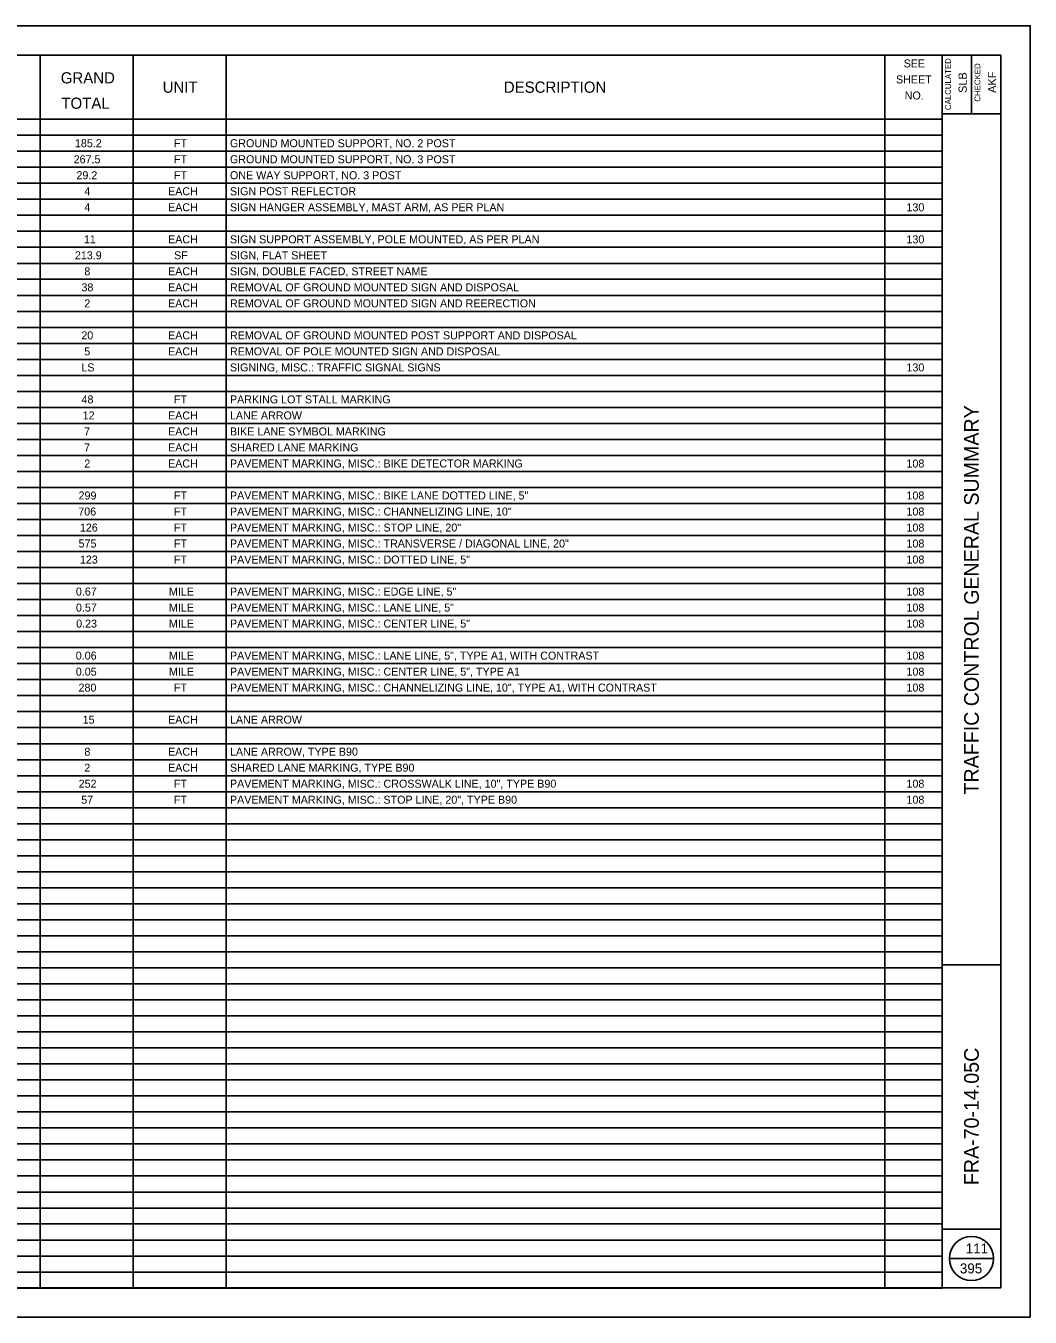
# Model space of a CAD drawing. Extents: x 1822379 to 1824724, y 710341 to 711455.
# Drawn here: x 1822396.01 to 1822413.11, y 711198.87 to 711220.87 of the extents above; entities that cross this region are included whole.
import ezdxf

# ---------------------------------------------------------------- set-up
doc = ezdxf.new("R2010")
doc.units = 0
for name, color, linetype in [('SH_Border', 7, 'Continuous'), ('SH_Cut_Line', 7, 'Continuous'), ('SH_Data', 7, 'Continuous'), ('SH_Text', 7, 'Continuous'), ('TX_P_20', 7, 'Continuous')]:
    doc.layers.add(name, color=color, linetype=linetype)

msp = doc.modelspace()

# ---------------------------------------------------------------- linework, layer by layer
at = {"layer": 'SH_Border'}
for p, q in [((1822411.613, 711199.366), (1822411.613, 711220.366)), ((1822412.113, 711220.366), (1822412.113, 711219.366)), ((1822411.613, 711219.366), (1822412.613, 711219.366)), ((1822411.613, 711204.866), (1822412.613, 711204.866)), ((1822411.613, 711200.366), (1822412.613, 711200.366))]:
    msp.add_line(p, q, dxfattribs=at)
msp.add_lwpolyline([(1822381.113, 711220.366), (1822412.613, 711220.366), (1822412.613, 711199.366), (1822381.113, 711199.366)], close=True, dxfattribs=at)
at = {"layer": 'SH_Cut_Line'}
msp.add_lwpolyline([(1822379.113, 711198.866), (1822413.113, 711198.866), (1822413.113, 711220.866), (1822379.113, 711220.866)], close=True, dxfattribs=at)
at = {"layer": 'SH_Data'}
for p, q in [((1822393.438, 711220.366), (1822411.613, 711220.366)), ((1822396.255, 711220.366), (1822396.255, 711199.362)), ((1822397.837, 711220.366), (1822397.837, 711199.362)), ((1822399.419, 711220.366), (1822399.419, 711199.362)), ((1822410.64, 711220.366), (1822410.64, 711199.362)), ((1822411.613, 711220.366), (1822411.613, 711199.362)), ((1822381.113, 711219.274), (1822411.613, 711219.274)), ((1822381.113, 711219.002), (1822411.613, 711219.002)), ((1822381.113, 711218.729), (1822411.613, 711218.729)), ((1822381.113, 711218.456), (1822411.613, 711218.456)), ((1822381.113, 711218.183), (1822411.613, 711218.183)), ((1822381.113, 711217.911), (1822411.613, 711217.911)), ((1822381.113, 711217.638), (1822411.613, 711217.638)), ((1822381.113, 711217.365), (1822411.613, 711217.365)), ((1822381.113, 711217.092), (1822411.613, 711217.092)), ((1822381.113, 711216.819), (1822411.613, 711216.819)), ((1822381.113, 711216.547), (1822411.613, 711216.547)), ((1822381.113, 711216.274), (1822411.613, 711216.274)), ((1822381.113, 711216.001), (1822411.613, 711216.001)), ((1822381.113, 711215.728), (1822411.613, 711215.728)), ((1822381.113, 711215.456), (1822411.613, 711215.456)), ((1822381.113, 711215.183), (1822411.613, 711215.183)), ((1822381.113, 711214.91), (1822411.613, 711214.91)), ((1822381.113, 711214.637), (1822411.613, 711214.637)), ((1822381.113, 711214.364), (1822411.613, 711214.364)), ((1822381.113, 711214.092), (1822411.613, 711214.092)), ((1822381.113, 711213.819), (1822411.613, 711213.819)), ((1822381.113, 711213.546), (1822411.613, 711213.546)), ((1822381.113, 711213.273), (1822411.613, 711213.273)), ((1822381.113, 711213.001), (1822411.613, 711213.001)), ((1822381.113, 711212.728), (1822411.613, 711212.728)), ((1822381.113, 711212.455), (1822411.613, 711212.455)), ((1822381.113, 711212.182), (1822411.613, 711212.182)), ((1822381.113, 711211.909), (1822411.613, 711211.909)), ((1822381.113, 711211.637), (1822411.613, 711211.637)), ((1822381.113, 711211.364), (1822411.613, 711211.364)), ((1822381.113, 711211.091), (1822411.613, 711211.091)), ((1822381.113, 711210.818), (1822411.613, 711210.818)), ((1822381.113, 711210.545), (1822411.613, 711210.545)), ((1822381.113, 711210.273), (1822411.613, 711210.273)), ((1822381.113, 711210), (1822411.613, 711210)), ((1822381.113, 711209.727), (1822411.613, 711209.727)), ((1822381.113, 711209.454), (1822411.613, 711209.454)), ((1822381.113, 711209.182), (1822411.613, 711209.182)), ((1822381.113, 711208.909), (1822411.613, 711208.909)), ((1822381.113, 711208.636), (1822411.613, 711208.636)), ((1822381.113, 711208.363), (1822411.613, 711208.363)), ((1822381.113, 711208.09), (1822411.613, 711208.09)), ((1822381.113, 711207.818), (1822411.613, 711207.818)), ((1822381.113, 711207.545), (1822411.613, 711207.545)), ((1822381.113, 711207.272), (1822411.613, 711207.272)), ((1822381.113, 711206.999), (1822411.613, 711206.999)), ((1822381.113, 711206.727), (1822411.613, 711206.727)), ((1822381.113, 711206.454), (1822411.613, 711206.454)), ((1822381.113, 711206.181), (1822411.613, 711206.181)), ((1822381.113, 711205.908), (1822411.613, 711205.908)), ((1822381.113, 711205.635), (1822411.613, 711205.635)), ((1822381.113, 711205.363), (1822411.613, 711205.363)), ((1822381.113, 711205.09), (1822411.613, 711205.09)), ((1822381.113, 711204.817), (1822411.613, 711204.817)), ((1822381.113, 711204.544), (1822411.613, 711204.544)), ((1822381.113, 711204.272), (1822411.613, 711204.272)), ((1822381.113, 711203.999), (1822411.613, 711203.999)), ((1822381.113, 711203.726), (1822411.613, 711203.726)), ((1822381.113, 711203.453), (1822411.613, 711203.453)), ((1822381.113, 711203.18), (1822411.613, 711203.18)), ((1822381.113, 711202.908), (1822411.613, 711202.908)), ((1822381.113, 711202.635), (1822411.613, 711202.635)), ((1822381.113, 711202.362), (1822411.613, 711202.362)), ((1822381.113, 711202.089), (1822411.613, 711202.089)), ((1822381.113, 711201.817), (1822411.613, 711201.817)), ((1822381.113, 711201.544), (1822411.613, 711201.544)), ((1822381.113, 711201.271), (1822411.613, 711201.271)), ((1822381.113, 711200.998), (1822411.613, 711200.998)), ((1822381.113, 711200.725), (1822411.613, 711200.725)), ((1822381.113, 711200.453), (1822411.613, 711200.453)), ((1822381.113, 711200.18), (1822411.613, 711200.18)), ((1822381.113, 711199.907), (1822411.613, 711199.907)), ((1822411.738, 711199.866), (1822412.488, 711199.866)), ((1822381.113, 711199.634), (1822411.613, 711199.634)), ((1822381.113, 711199.362), (1822411.613, 711199.362))]:
    msp.add_line(p, q, dxfattribs=at)
msp.add_circle((1822412.113, 711199.866), 0.375, dxfattribs=at)

# ---------------------------------------------------------------- texts
for s, height, p in [('CALCULATED', 0.1, (1822411.765, 711219.43)), ('CHECKED', 0.1, (1822412.265, 711219.573)), ('SLB', 0.14, (1822412.033, 711219.722)), ('AKF', 0.14, (1822412.533, 711219.723)), ('TRAFFIC CONTROL GENERAL SUMMARY', 0.25, (1822412.238, 711207.77)), ('FRA-70-14.05C', 0.25, (1822412.238, 711201.115))]:
    msp.add_text(s, height=height, rotation=90, dxfattribs=at).set_placement(p)
at = {"layer": 'SH_Text'}
for s, height, p in [('SEE', 0.1364, (1822410.958, 711220.157)), ('GRAND', 0.1909, (1822396.604, 711219.884)), ('SHEET', 0.1364, (1822410.828, 711219.884)), ('UNIT', 0.1909, (1822398.339, 711219.725)), ('DESCRIPTION', 0.19095, (1822404.149, 711219.725)), ('NO.', 0.1364, (1822410.976, 711219.611)), ('TOTAL', 0.1909, (1822396.614, 711219.452)), ('185.2', 0.1364, (1822396.845, 711218.797)), ('FT', 0.1364, (1822398.53, 711218.797)), ('GROUND MOUNTED SUPPORT, NO. 2 POST', 0.13639, (1822399.485, 711218.797)), ('267.5', 0.1364, (1822396.823, 711218.524)), ('FT', 0.1364, (1822398.53, 711218.524)), ('GROUND MOUNTED SUPPORT, NO. 3 POST', 0.13639, (1822399.485, 711218.524)), ('29.2', 0.1364, (1822396.871, 711218.252)), ('FT', 0.1364, (1822398.53, 711218.252)), ('ONE WAY SUPPORT, NO. 3 POST', 0.13639, (1822399.485, 711218.252)), ('4', 0.136, (1822397.005, 711217.979)), ('EACH', 0.1364, (1822398.431, 711217.979)), ('SIGN POST REFLECTOR', 0.13639, (1822399.485, 711217.979)), ('4', 0.136, (1822397.005, 711217.706)), ('EACH', 0.1364, (1822398.431, 711217.706)), ('SIGN HANGER ASSEMBLY, MAST ARM, AS PER PLAN', 0.13639, (1822399.485, 711217.706)), ('130', 0.1364, (1822411.006, 711217.706)), ('11', 0.1364, (1822396.997, 711217.16)), ('EACH', 0.1364, (1822398.431, 711217.16)), ('SIGN SUPPORT ASSEMBLY, POLE MOUNTED, AS PER PLAN', 0.13639, (1822399.485, 711217.16)), ('130', 0.1364, (1822411.006, 711217.16)), ('213.9', 0.1364, (1822396.844, 711216.888)), ('SF', 0.1364, (1822398.533, 711216.888)), ('SIGN, FLAT SHEET', 0.13639, (1822399.485, 711216.888)), ('8', 0.136, (1822397.006, 711216.615)), ('EACH', 0.1364, (1822398.431, 711216.615)), ('SIGN, DOUBLE FACED, STREET NAME', 0.13639, (1822399.485, 711216.615)), ('38', 0.1364, (1822396.956, 711216.342)), ('EACH', 0.1364, (1822398.431, 711216.342)), ('REMOVAL OF GROUND MOUNTED SIGN AND DISPOSAL', 0.13639, (1822399.485, 711216.342)), ('2', 0.136, (1822397.004, 711216.069)), ('EACH', 0.1364, (1822398.431, 711216.069)), ('REMOVAL OF GROUND MOUNTED SIGN AND REERECTION', 0.13639, (1822399.485, 711216.069)), ('20', 0.1364, (1822396.954, 711215.524)), ('EACH', 0.1364, (1822398.431, 711215.524)), ('REMOVAL OF GROUND MOUNTED POST SUPPORT AND DISPOSAL', 0.13639, (1822399.485, 711215.524)), ('5', 0.136, (1822397.004, 711215.251)), ('EACH', 0.1364, (1822398.431, 711215.251)), ('REMOVAL OF POLE MOUNTED SIGN AND DISPOSAL', 0.13639, (1822399.485, 711215.251)), ('LS', 0.1364, (1822396.954, 711214.978)), ('SIGNING, MISC.: TRAFFIC SIGNAL SIGNS', 0.13639, (1822399.485, 711214.978)), ('130', 0.1364, (1822411.006, 711214.978)), ('48', 0.1364, (1822396.957, 711214.433)), ('FT', 0.1364, (1822398.53, 711214.433)), ('PARKING LOT STALL MARKING', 0.13639, (1822399.485, 711214.433)), ('12', 0.1364, (1822396.978, 711214.16)), ('EACH', 0.1364, (1822398.431, 711214.16)), ('LANE ARROW', 0.1364, (1822399.485, 711214.16)), ('7', 0.136, (1822397.001, 711213.887)), ('EACH', 0.1364, (1822398.431, 711213.887)), ('BIKE LANE SYMBOL MARKING', 0.13639, (1822399.485, 711213.887)), ('7', 0.136, (1822397.001, 711213.614)), ('EACH', 0.1364, (1822398.431, 711213.614)), ('SHARED LANE MARKING', 0.13639, (1822399.485, 711213.614)), ('2', 0.136, (1822397.004, 711213.341)), ('EACH', 0.1364, (1822398.431, 711213.341)), ('PAVEMENT MARKING, MISC.: BIKE DETECTOR MARKING', 0.13639, (1822399.485, 711213.341)), ('108', 0.1364, (1822411.006, 711213.341)), ('299', 0.1364, (1822396.907, 711212.796)), ('FT', 0.1364, (1822398.53, 711212.796)), ('PAVEMENT MARKING, MISC.: BIKE LANE DOTTED LINE, 5"', 0.13639, (1822399.485, 711212.796)), ('108', 0.1364, (1822411.006, 711212.796)), ('706', 0.1364, (1822396.902, 711212.523)), ('FT', 0.1364, (1822398.53, 711212.523)), ('PAVEMENT MARKING, MISC.: CHANNELIZING LINE, 10"', 0.13639, (1822399.485, 711212.523)), ('108', 0.1364, (1822411.006, 711212.523)), ('126', 0.1364, (1822396.929, 711212.25)), ('FT', 0.1364, (1822398.53, 711212.25)), ('PAVEMENT MARKING, MISC.: STOP LINE, 20"', 0.13639, (1822399.485, 711212.25)), ('108', 0.1364, (1822411.006, 711212.25)), ('575', 0.1364, (1822396.907, 711211.978)), ('FT', 0.1364, (1822398.53, 711211.978)), ('PAVEMENT MARKING, MISC.: TRANSVERSE / DIAGONAL LINE, 20"', 0.13639, (1822399.485, 711211.978)), ('108', 0.1364, (1822411.006, 711211.978)), ('123', 0.1364, (1822396.929, 711211.705)), ('FT', 0.1364, (1822398.53, 711211.705)), ('PAVEMENT MARKING, MISC.: DOTTED LINE, 5"', 0.13639, (1822399.485, 711211.705)), ('108', 0.1364, (1822411.006, 711211.705)), ('0.67', 0.1364, (1822396.862, 711211.159)), ('MILE', 0.1364, (1822398.446, 711211.159)), ('PAVEMENT MARKING, MISC.: EDGE LINE, 5"', 0.13639, (1822399.485, 711211.159)), ('108', 0.1364, (1822411.006, 711211.159)), ('0.57', 0.1364, (1822396.862, 711210.886)), ('MILE', 0.1364, (1822398.446, 711210.886)), ('PAVEMENT MARKING, MISC.: LANE LINE, 5"', 0.13639, (1822399.485, 711210.886)), ('108', 0.1364, (1822411.006, 711210.886)), ('0.23', 0.1364, (1822396.866, 711210.614)), ('MILE', 0.1364, (1822398.446, 711210.614)), ('PAVEMENT MARKING, MISC.: CENTER LINE, 5"', 0.13639, (1822399.485, 711210.614)), ('108', 0.1364, (1822411.006, 711210.614)), ('0.06', 0.1364, (1822396.859, 711210.068)), ('MILE', 0.1364, (1822398.446, 711210.068)), ('PAVEMENT MARKING, MISC.: LANE LINE, 5", TYPE A1, WITH CONTRAST', 0.13639, (1822399.485, 711210.068)), ('108', 0.1364, (1822411.006, 711210.068)), ('0.05', 0.1364, (1822396.86, 711209.795)), ('MILE', 0.1364, (1822398.446, 711209.795)), ('PAVEMENT MARKING, MISC.: CENTER LINE, 5", TYPE A1', 0.13639, (1822399.485, 711209.795)), ('108', 0.1364, (1822411.006, 711209.795)), ('280', 0.1364, (1822396.906, 711209.523)), ('FT', 0.1364, (1822398.53, 711209.523)), ('PAVEMENT MARKING, MISC.: CHANNELIZING LINE, 10", TYPE A1, WITH CONTRAST', 0.13639, (1822399.485, 711209.523)), ('108', 0.1364, (1822411.006, 711209.523)), ('15', 0.1364, (1822396.977, 711208.977)), ('EACH', 0.1364, (1822398.431, 711208.977)), ('LANE ARROW', 0.1364, (1822399.485, 711208.977)), ('8', 0.136, (1822397.006, 711208.431)), ('EACH', 0.1364, (1822398.431, 711208.431)), ('LANE ARROW, TYPE B90', 0.13639, (1822399.485, 711208.431)), ('2', 0.136, (1822397.004, 711208.159)), ('EACH', 0.1364, (1822398.431, 711208.159)), ('SHARED LANE MARKING, TYPE B90', 0.13639, (1822399.485, 711208.159)), ('252', 0.1364, (1822396.908, 711207.886)), ('FT', 0.1364, (1822398.53, 711207.886)), ('PAVEMENT MARKING, MISC.: CROSSWALK LINE, 10", TYPE B90', 0.13639, (1822399.485, 711207.886)), ('108', 0.1364, (1822411.006, 711207.886)), ('57', 0.1364, (1822396.952, 711207.613)), ('FT', 0.1364, (1822398.53, 711207.613)), ('PAVEMENT MARKING, MISC.: STOP LINE, 20", TYPE B90', 0.13639, (1822399.485, 711207.613)), ('108', 0.1364, (1822411.006, 711207.613))]:
    msp.add_text(s, height=height, dxfattribs=at).set_placement(p)
at = {"layer": 'TX_P_20'}
for s, p in [('111', (1822412.016, 711199.951)), ('395', (1822411.916, 711199.611))]:
    msp.add_text(s, height=0.17, dxfattribs=at).set_placement(p)

doc.saveas('drawing.dxf')
